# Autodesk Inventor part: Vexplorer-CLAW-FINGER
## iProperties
Created: 2007-10
Part Number: Vexplorer-CLAW-FINGER
Document SubType Name: Modeling
Material: ABS Plastic
Density: 1.06 g/cm^3
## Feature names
1. Base1
